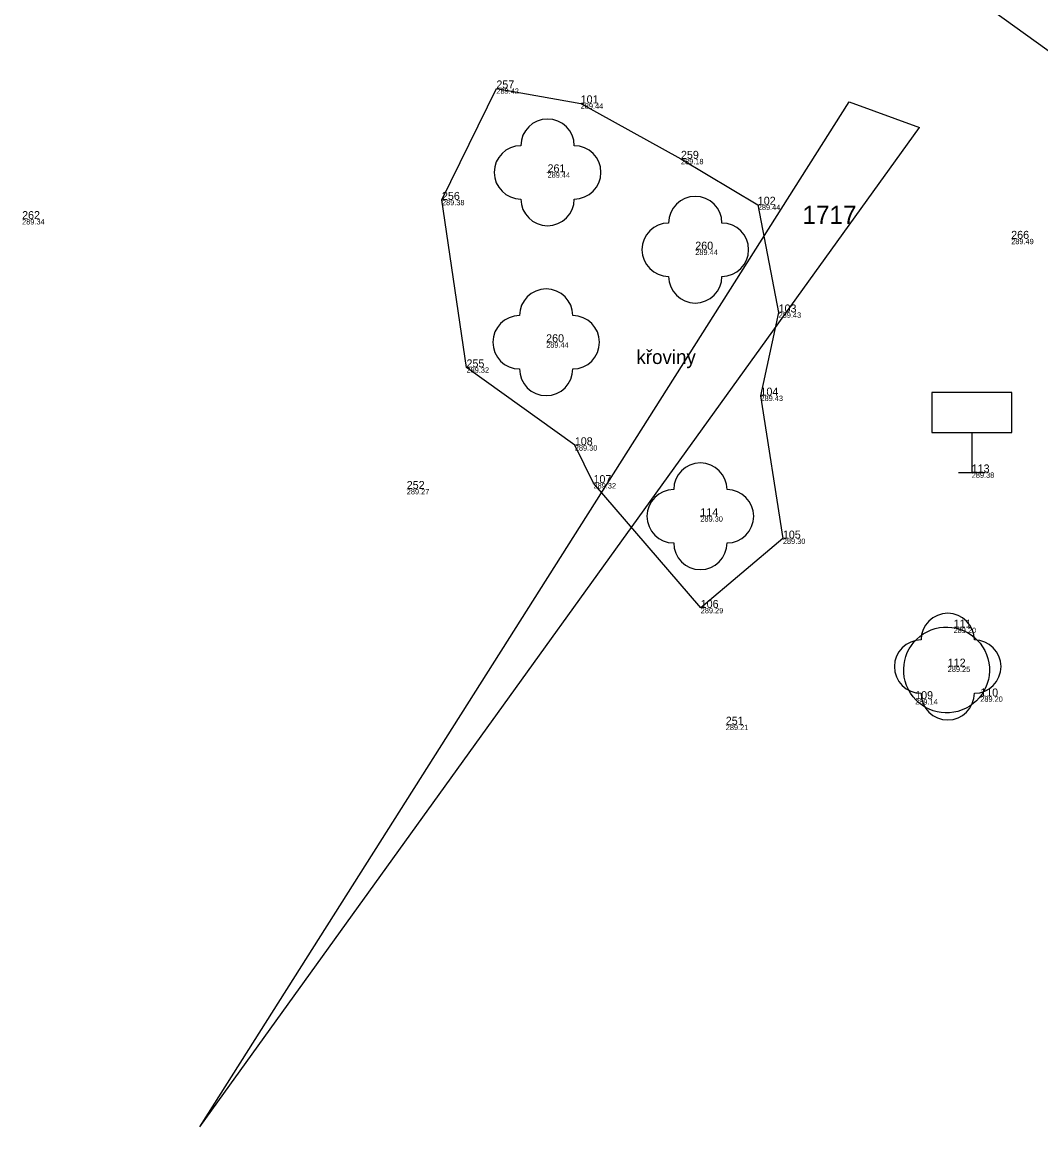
# Model space of a CAD drawing. Extents: x -805057 to -804930, y -994399 to -994240.
# Drawn here: x -805016.64 to -804997.54, y -994363.31 to -994342.6 of the extents above; entities that cross this region are included whole.
import ezdxf

# ---------------------------------------------------------------- set-up
doc = ezdxf.new("R2010")
doc.units = 0
for name, color, linetype in [('bod cislo', 7, 'Continuous'), ('bod pozice', 7, 'Continuous'), ('bod výška', 7, 'Continuous'), ('Katastralni mapa', 7, 'Continuous'), ('komunikace', 7, 'Continuous'), ('lavice', 7, 'Continuous'), ('označník', 7, 'Continuous'), ('popis', 7, 'Continuous'), ('strom', 7, 'Continuous')]:
    doc.layers.add(name, color=color, linetype=linetype)

msp = doc.modelspace()

# ---------------------------------------------------------------- linework, layer by layer
at = {"layer": 'bod pozice'}
for p, q in [((-805007.75, -994343.84), (-805007.75, -994343.84)), ((-805006.17, -994344.12), (-805006.17, -994344.12)), ((-805004.29, -994345.16), (-805004.29, -994345.16)), ((-805006.791, -994345.413), (-805006.791, -994345.413)), ((-805008.77, -994345.93), (-805008.77, -994345.93)), ((-805002.85, -994346.02), (-805002.85, -994346.02)), ((-805016.64, -994346.29), (-805016.64, -994346.29)), ((-804998.1, -994346.66), (-804998.1, -994346.66)), ((-805004.022, -994346.863), (-805004.022, -994346.863)), ((-805002.46, -994348.04), (-805002.46, -994348.04)), ((-805006.817, -994348.599), (-805006.817, -994348.599)), ((-805008.31, -994349.07), (-805008.31, -994349.07)), ((-805002.8, -994349.6), (-805002.8, -994349.6)), ((-805006.28, -994350.53), (-805006.28, -994350.53)), ((-804998.84, -994351.04), (-804998.84, -994351.04)), ((-805009.43, -994351.35), (-805009.43, -994351.35)), ((-805005.93, -994351.24), (-805005.93, -994351.24)), ((-805003.927, -994351.861), (-805003.927, -994351.861)), ((-805002.38, -994352.28), (-805002.38, -994352.28)), ((-805003.92, -994353.58), (-805003.92, -994353.58)), ((-804999.18, -994353.95), (-804999.18, -994353.95)), ((-804999.29, -994354.68), (-804999.29, -994354.68)), ((-804999.9, -994355.29), (-804999.9, -994355.29)), ((-804998.68, -994355.24), (-804998.68, -994355.24)), ((-805003.45, -994355.77), (-805003.45, -994355.77))]:
    msp.add_line(p, q, dxfattribs=at)
at = {"layer": 'Katastralni mapa'}
for points in [[(-805013.31, -994363.31), (-805001.14, -994344.09)], [(-805001.14, -994344.09), (-804999.82, -994344.57)], [(-805013.31, -994363.31), (-804999.82, -994344.57)]]:
    msp.add_lwpolyline(points, dxfattribs=at)
at = {"layer": 'komunikace'}
msp.add_line((-805005.97, -994336.96), (-804995.46, -994344.53), dxfattribs=at)
at = {"layer": 'lavice'}
msp.add_ellipse((-804999.312, -994354.743), major_axis=(-0.291, 0.75), ratio=0.998655, dxfattribs=at)
at = {"layer": 'označník'}
for p, q in [((-804998.84, -994350.29), (-804998.84, -994351.04)), ((-804999.09, -994351.04), (-804998.59, -994351.04))]:
    msp.add_line(p, q, dxfattribs=at)
msp.add_lwpolyline([(-804999.59, -994350.29), (-804998.09, -994350.29), (-804998.09, -994349.54), (-804999.59, -994349.54)], close=True, dxfattribs=at)
at = {"layer": 'strom'}
for p, q in [((-805008.77, -994345.93), (-805007.75, -994343.84)), ((-805007.75, -994343.84), (-805006.17, -994344.12)), ((-805006.17, -994344.12), (-805004.29, -994345.16)), ((-805004.29, -994345.16), (-805002.85, -994346.02)), ((-805008.31, -994349.07), (-805008.77, -994345.93)), ((-805002.85, -994346.02), (-805002.46, -994348.04)), ((-805002.46, -994348.04), (-805002.8, -994349.6)), ((-805006.28, -994350.53), (-805008.31, -994349.07)), ((-805002.8, -994349.6), (-805002.38, -994352.28)), ((-805005.93, -994351.24), (-805006.28, -994350.53)), ((-805003.92, -994353.58), (-805005.93, -994351.24)), ((-805002.38, -994352.28), (-805003.92, -994353.58))]:
    msp.add_line(p, q, dxfattribs=at)
for centre in [(-805006.791, -994345.413), (-805004.022, -994346.863), (-805006.817, -994348.599), (-805003.927, -994351.861), (-804999.29, -994354.68)]:
    msp.add_circle(centre, 0.0005, dxfattribs=at)
for centre, start, end in [((-805006.791, -994344.913), 0, 180), ((-805007.291, -994345.413), 90, 270), ((-805006.291, -994345.413), 270, 90), ((-805006.791, -994345.913), 180, 360), ((-805004.022, -994346.363), 0, 180), ((-805004.522, -994346.863), 90, 270), ((-805003.522, -994346.863), 270, 90), ((-805004.022, -994347.363), 180, 360), ((-805006.817, -994348.099), 0, 180), ((-805007.317, -994348.599), 90, 270), ((-805006.317, -994348.599), 270, 90), ((-805006.817, -994349.099), 180, 360), ((-805003.927, -994351.361), 0, 180), ((-805004.427, -994351.861), 90, 270), ((-805003.427, -994351.861), 270, 90), ((-805003.927, -994352.361), 180, 360), ((-804999.29, -994354.18), 0, 180), ((-804999.79, -994354.68), 90, 270), ((-804998.79, -994354.68), 270, 90), ((-804999.29, -994355.18), 180, 360)]:
    msp.add_arc(centre, 0.5, start, end, dxfattribs=at)

# ---------------------------------------------------------------- texts
at = {"layer": 'bod cislo'}
for s, p in [('257    ', (-805007.75, -994343.84)), ('101    ', (-805006.17, -994344.12)), ('259    ', (-805004.29, -994345.16)), ('261', (-805006.791, -994345.413)), ('256    ', (-805008.77, -994345.93)), ('102    ', (-805002.85, -994346.02)), ('262    ', (-805016.64, -994346.29)), ('266    ', (-804998.1, -994346.66)), ('260 ', (-805004.022, -994346.863)), ('103    ', (-805002.46, -994348.04)), ('260 ', (-805006.817, -994348.599)), ('255    ', (-805008.31, -994349.07)), ('104    ', (-805002.8, -994349.6)), ('108    ', (-805006.28, -994350.53)), ('113    ', (-804998.84, -994351.04)), ('107    ', (-805005.93, -994351.24)), ('252    ', (-805009.43, -994351.35)), ('114', (-805003.927, -994351.861)), ('105    ', (-805002.38, -994352.28)), ('106    ', (-805003.92, -994353.58)), ('111    ', (-804999.18, -994353.95)), ('112    ', (-804999.29, -994354.68)), ('110    ', (-804998.68, -994355.24)), ('109    ', (-804999.9, -994355.29)), ('251    ', (-805003.45, -994355.77))]:
    msp.add_text(s, height=0.15, dxfattribs=at).set_placement(p)
at = {"layer": 'bod výška'}
for s, p in [('289.42  ', (-805007.75, -994343.94)), ('289.44  ', (-805006.17, -994344.22)), ('289.18  ', (-805004.29, -994345.26)), ('289.44  ', (-805006.791, -994345.513)), ('289.38  ', (-805008.77, -994346.03)), ('289.44  ', (-805002.85, -994346.12)), ('289.34  ', (-805016.64, -994346.39)), ('289.49  ', (-804998.1, -994346.76)), ('289.44  ', (-805004.022, -994346.963)), ('289.43  ', (-805002.46, -994348.14)), ('289.44  ', (-805006.817, -994348.699)), ('289.32  ', (-805008.31, -994349.17)), ('289.43  ', (-805002.8, -994349.7)), ('289.30  ', (-805006.28, -994350.63)), ('289.38  ', (-804998.84, -994351.14)), ('289.27  ', (-805009.43, -994351.45)), ('289.32  ', (-805005.93, -994351.34)), ('289.30  ', (-805003.927, -994351.961)), ('289.30  ', (-805002.38, -994352.38)), ('289.29  ', (-805003.92, -994353.68)), ('289.20  ', (-804999.18, -994354.05)), ('289.25  ', (-804999.29, -994354.78)), ('289.14  ', (-804999.9, -994355.39)), ('289.20  ', (-804998.68, -994355.34)), ('289.21  ', (-805003.45, -994355.87))]:
    msp.add_text(s, height=0.1, dxfattribs=at).set_placement(p)
at = {"layer": 'Katastralni mapa'}
msp.add_text('1717', height=0.34, dxfattribs=at).set_placement((-805002.013, -994346.38))
at = {"layer": 'popis'}
msp.add_text('křoviny', height=0.2629, dxfattribs=at).set_placement((-805005.125, -994349.006))

doc.saveas('drawing.dxf')
